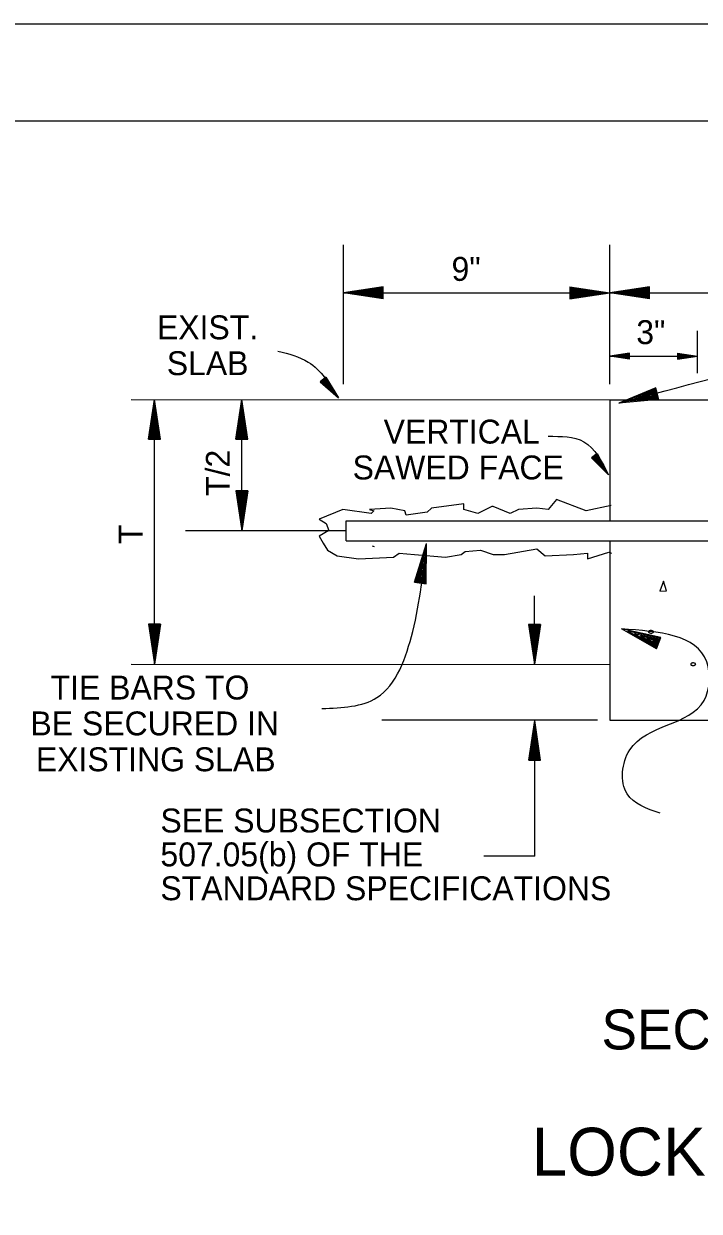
# Model space of a CAD drawing. Extents: x 1375738 to 1375905, y 380661 to 380875.
# Drawn here: x 1375777.18 to 1375790.75, y 380850.89 to 380874.73 of the extents above; entities that cross this region are included whole.
import ezdxf

# ---------------------------------------------------------------- set-up
doc = ezdxf.new("R2010")
doc.units = 0
for name, color, linetype in [('R_Border', 7, 'Continuous'), ('R_Draft', 7, 'Continuous'), ('R_No Plot', 7, 'Continuous')]:
    doc.layers.add(name, color=color, linetype=linetype)

msp = doc.modelspace()

# ---------------------------------------------------------------- linework, layer by layer
at = {"layer": 'R_Border'}
msp.add_line((1375744.419, 380872.783), (1375902.509, 380872.783), dxfattribs=at)
at = {"layer": 'R_Draft'}
for p, q in [((1375783.599, 380867.494), (1375783.599, 380870.291)), ((1375788.949, 380867.494), (1375788.949, 380870.291)), ((1375784.399, 380869.449), (1375783.599, 380869.329)), ((1375783.599, 380869.329), (1375788.949, 380869.329)), ((1375784.399, 380869.209), (1375783.599, 380869.329)), ((1375784.399, 380869.429), (1375783.733, 380869.329)), ((1375784.399, 380869.229), (1375783.733, 380869.329)), ((1375784.399, 380869.409), (1375783.87, 380869.329)), ((1375784.399, 380869.25), (1375783.87, 380869.329)), ((1375784.399, 380869.389), (1375784.004, 380869.329)), ((1375784.399, 380869.27), (1375784.004, 380869.329)), ((1375784.399, 380869.369), (1375784.139, 380869.329)), ((1375784.399, 380869.291), (1375784.139, 380869.329)), ((1375784.399, 380869.348), (1375784.273, 380869.329)), ((1375784.399, 380869.311), (1375784.273, 380869.329)), ((1375784.399, 380869.209), (1375784.399, 380869.449)), ((1375788.149, 380869.449), (1375788.949, 380869.329)), ((1375788.149, 380869.449), (1375788.149, 380869.209)), ((1375788.149, 380869.429), (1375788.815, 380869.329)), ((1375788.149, 380869.409), (1375788.678, 380869.329)), ((1375788.149, 380869.389), (1375788.544, 380869.329)), ((1375788.149, 380869.368), (1375788.409, 380869.329)), ((1375788.149, 380869.348), (1375788.275, 380869.329)), ((1375788.149, 380869.209), (1375788.949, 380869.329)), ((1375788.149, 380869.29), (1375788.409, 380869.329)), ((1375788.149, 380869.25), (1375788.678, 380869.329)), ((1375788.149, 380869.229), (1375788.815, 380869.329)), ((1375788.149, 380869.27), (1375788.544, 380869.329)), ((1375788.149, 380869.311), (1375788.275, 380869.329)), ((1375789.749, 380869.449), (1375788.949, 380869.329)), ((1375788.949, 380869.329), (1375794.403, 380869.329)), ((1375789.749, 380869.209), (1375788.949, 380869.329)), ((1375789.749, 380869.429), (1375789.082, 380869.329)), ((1375789.749, 380869.229), (1375789.082, 380869.329)), ((1375789.749, 380869.409), (1375789.22, 380869.329)), ((1375789.749, 380869.25), (1375789.22, 380869.329)), ((1375789.749, 380869.389), (1375789.353, 380869.329)), ((1375789.749, 380869.27), (1375789.353, 380869.329)), ((1375789.749, 380869.369), (1375789.489, 380869.329)), ((1375789.749, 380869.291), (1375789.489, 380869.329)), ((1375789.749, 380869.348), (1375789.622, 380869.329)), ((1375789.749, 380869.311), (1375789.622, 380869.329)), ((1375789.749, 380869.209), (1375789.749, 380869.449)), ((1375790.71, 380867.719), (1375790.71, 380868.567)), ((1375789.349, 380868.119), (1375788.949, 380868.059)), ((1375788.949, 380868.059), (1375790.71, 380868.059)), ((1375789.349, 380867.999), (1375788.949, 380868.059)), ((1375789.349, 380868.109), (1375789.016, 380868.059)), ((1375789.349, 380868.009), (1375789.016, 380868.059)), ((1375789.349, 380868.098), (1375789.084, 380868.059)), ((1375789.349, 380868.019), (1375789.084, 380868.059)), ((1375789.349, 380868.088), (1375789.151, 380868.059)), ((1375789.349, 380868.029), (1375789.151, 380868.059)), ((1375789.349, 380868.078), (1375789.219, 380868.059)), ((1375789.349, 380868.039), (1375789.219, 380868.059)), ((1375789.349, 380868.068), (1375789.286, 380868.059)), ((1375789.349, 380868.049), (1375789.286, 380868.059)), ((1375789.349, 380867.999), (1375789.349, 380868.119)), ((1375790.31, 380868.119), (1375790.71, 380868.059)), ((1375790.31, 380868.119), (1375790.31, 380867.999)), ((1375790.31, 380868.109), (1375790.643, 380868.059)), ((1375790.31, 380868.098), (1375790.574, 380868.059)), ((1375790.31, 380868.088), (1375790.508, 380868.059)), ((1375790.31, 380868.078), (1375790.44, 380868.059)), ((1375790.31, 380868.068), (1375790.373, 380868.059)), ((1375790.31, 380867.999), (1375790.71, 380868.059)), ((1375790.31, 380868.039), (1375790.44, 380868.059)), ((1375790.31, 380868.019), (1375790.574, 380868.059)), ((1375790.31, 380868.009), (1375790.643, 380868.059)), ((1375790.31, 380868.029), (1375790.508, 380868.059)), ((1375790.31, 380868.049), (1375790.373, 380868.059)), ((1375783.244, 380867.635), (1375783.134, 380867.542)), ((1375783.171, 380867.573), (1375783.29, 380867.469)), ((1375783.18, 380867.581), (1375783.238, 380867.53)), ((1375783.198, 380867.595), (1375783.238, 380867.53)), ((1375783.207, 380867.603), (1375783.29, 380867.469)), ((1375783.216, 380867.611), (1375783.342, 380867.407)), ((1375783.226, 380867.619), (1375783.394, 380867.346)), ((1375783.235, 380867.627), (1375783.448, 380867.283)), ((1375783.244, 380867.635), (1375783.499, 380867.222)), ((1375783.134, 380867.542), (1375783.499, 380867.222)), ((1375783.143, 380867.549), (1375783.448, 380867.283)), ((1375783.153, 380867.557), (1375783.394, 380867.346)), ((1375783.162, 380867.565), (1375783.342, 380867.407)), ((1375789.878, 380867.422), (1375789.131, 380867.111)), ((1375789.883, 380867.402), (1375789.261, 380867.144)), ((1375789.888, 380867.383), (1375789.394, 380867.177)), ((1375789.893, 380867.363), (1375789.524, 380867.209)), ((1375789.898, 380867.343), (1375789.655, 380867.242)), ((1375789.936, 380867.189), (1375789.878, 380867.422)), ((1375779.334, 380867.189), (1375788.952, 380867.184)), ((1375779.684, 380866.388), (1375779.804, 380867.188)), ((1375779.804, 380861.875), (1375779.804, 380867.188)), ((1375779.924, 380866.388), (1375779.804, 380867.188)), ((1375781.436, 380866.388), (1375781.556, 380867.188)), ((1375781.556, 380864.554), (1375781.556, 380867.188)), ((1375781.676, 380866.388), (1375781.556, 380867.188)), ((1375788.949, 380867.184), (1375798.81, 380867.184)), ((1375788.949, 380867.184), (1375788.949, 380864.752)), ((1375789.936, 380867.189), (1375789.131, 380867.111)), ((1375789.932, 380867.208), (1375789.261, 380867.144)), ((1375789.927, 380867.228), (1375789.394, 380867.177)), ((1375789.922, 380867.247), (1375789.524, 380867.209)), ((1375789.917, 380867.268), (1375789.655, 380867.242)), ((1375789.903, 380867.324), (1375789.785, 380867.275)), ((1375789.912, 380867.287), (1375789.785, 380867.275)), ((1375779.704, 380866.388), (1375779.804, 380867.055)), ((1375779.724, 380866.388), (1375779.804, 380866.917)), ((1375779.904, 380866.388), (1375779.804, 380867.055)), ((1375779.883, 380866.388), (1375779.804, 380866.917)), ((1375781.456, 380866.388), (1375781.556, 380867.055)), ((1375781.476, 380866.388), (1375781.556, 380866.917)), ((1375781.656, 380866.388), (1375781.556, 380867.055)), ((1375781.635, 380866.388), (1375781.556, 380866.917)), ((1375779.744, 380866.388), (1375779.804, 380866.784)), ((1375779.765, 380866.388), (1375779.804, 380866.648)), ((1375779.863, 380866.388), (1375779.804, 380866.784)), ((1375779.843, 380866.388), (1375779.804, 380866.648)), ((1375781.496, 380866.388), (1375781.556, 380866.784)), ((1375781.517, 380866.388), (1375781.556, 380866.648)), ((1375781.615, 380866.388), (1375781.556, 380866.784)), ((1375781.595, 380866.388), (1375781.556, 380866.648)), ((1375779.684, 380866.388), (1375779.924, 380866.388)), ((1375779.785, 380866.388), (1375779.804, 380866.515)), ((1375779.822, 380866.388), (1375779.804, 380866.515)), ((1375781.436, 380866.388), (1375781.676, 380866.388)), ((1375781.537, 380866.388), (1375781.556, 380866.515)), ((1375781.574, 380866.388), (1375781.556, 380866.515)), ((1375788.695, 380866.103), (1375788.58, 380866.017)), ((1375788.58, 380866.017), (1375788.925, 380865.676)), ((1375788.589, 380866.024), (1375788.877, 380865.74)), ((1375788.599, 380866.031), (1375788.828, 380865.806)), ((1375788.608, 380866.038), (1375788.78, 380865.87)), ((1375788.618, 380866.046), (1375788.731, 380865.935)), ((1375788.628, 380866.053), (1375788.683, 380865.999)), ((1375788.646, 380866.067), (1375788.683, 380865.999)), ((1375788.656, 380866.074), (1375788.731, 380865.935)), ((1375788.666, 380866.081), (1375788.78, 380865.87)), ((1375788.676, 380866.089), (1375788.828, 380865.806)), ((1375788.685, 380866.096), (1375788.877, 380865.74)), ((1375788.695, 380866.103), (1375788.925, 380865.676)), ((1375781.436, 380865.354), (1375781.556, 380864.554)), ((1375781.676, 380865.354), (1375781.436, 380865.354)), ((1375781.456, 380865.354), (1375781.556, 380864.687)), ((1375781.476, 380865.354), (1375781.556, 380864.825)), ((1375781.496, 380865.354), (1375781.556, 380864.958)), ((1375781.516, 380865.354), (1375781.556, 380865.094)), ((1375781.537, 380865.354), (1375781.556, 380865.227)), ((1375781.676, 380865.354), (1375781.556, 380864.554)), ((1375781.594, 380865.354), (1375781.556, 380865.094)), ((1375781.635, 380865.354), (1375781.556, 380864.825)), ((1375781.656, 380865.354), (1375781.556, 380864.687)), ((1375781.615, 380865.354), (1375781.556, 380864.958)), ((1375781.574, 380865.354), (1375781.556, 380865.227)), ((1375783.657, 380864.755), (1375794.47, 380864.749)), ((1375783.657, 380864.353), (1375783.657, 380864.755)), ((1375783.657, 380864.554), (1375780.426, 380864.554)), ((1375783.657, 380864.353), (1375794.469, 380864.347)), ((1375785.024, 380863.523), (1375785.266, 380864.295)), ((1375785.261, 380863.487), (1375785.266, 380864.295)), ((1375788.949, 380864.351), (1375788.949, 380860.751)), ((1375785.044, 380863.521), (1375785.245, 380864.163)), ((1375785.064, 380863.517), (1375785.224, 380864.027)), ((1375785.221, 380863.493), (1375785.224, 380864.027)), ((1375785.241, 380863.489), (1375785.245, 380864.163)), ((1375785.084, 380863.514), (1375785.204, 380863.896)), ((1375785.104, 380863.511), (1375785.183, 380863.762)), ((1375785.181, 380863.499), (1375785.183, 380863.762)), ((1375785.202, 380863.496), (1375785.204, 380863.896)), ((1375785.024, 380863.523), (1375785.261, 380863.487)), ((1375785.124, 380863.508), (1375785.162, 380863.63)), ((1375785.161, 380863.502), (1375785.162, 380863.63)), ((1375787.44, 380861.874), (1375787.44, 380863.248)), ((1375779.684, 380862.675), (1375779.804, 380861.875)), ((1375779.924, 380862.675), (1375779.684, 380862.675)), ((1375779.704, 380862.675), (1375779.804, 380862.009)), ((1375779.724, 380862.675), (1375779.804, 380862.147)), ((1375779.744, 380862.675), (1375779.804, 380862.28)), ((1375779.764, 380862.675), (1375779.804, 380862.415)), ((1375779.785, 380862.675), (1375779.804, 380862.549)), ((1375779.924, 380862.675), (1375779.804, 380861.875)), ((1375779.842, 380862.675), (1375779.804, 380862.415)), ((1375779.883, 380862.675), (1375779.804, 380862.147)), ((1375779.904, 380862.675), (1375779.804, 380862.009)), ((1375779.863, 380862.675), (1375779.804, 380862.28)), ((1375779.822, 380862.675), (1375779.804, 380862.549)), ((1375787.32, 380862.674), (1375787.44, 380861.874)), ((1375787.56, 380862.674), (1375787.32, 380862.674)), ((1375787.34, 380862.674), (1375787.44, 380862.008)), ((1375787.36, 380862.674), (1375787.44, 380862.145)), ((1375787.38, 380862.674), (1375787.44, 380862.279)), ((1375787.401, 380862.674), (1375787.44, 380862.414)), ((1375787.421, 380862.674), (1375787.44, 380862.548)), ((1375787.56, 380862.674), (1375787.44, 380861.874)), ((1375787.479, 380862.674), (1375787.44, 380862.414)), ((1375787.52, 380862.674), (1375787.44, 380862.145)), ((1375787.54, 380862.674), (1375787.44, 380862.008)), ((1375787.5, 380862.674), (1375787.44, 380862.279)), ((1375787.459, 380862.674), (1375787.44, 380862.548)), ((1375789.889, 380862.183), (1375789.186, 380862.583)), ((1375789.976, 380862.407), (1375789.186, 380862.583)), ((1375789.896, 380862.201), (1375789.311, 380862.535)), ((1375789.968, 380862.388), (1375789.311, 380862.535)), ((1375789.961, 380862.369), (1375789.439, 380862.485)), ((1375789.904, 380862.221), (1375789.439, 380862.485)), ((1375789.911, 380862.239), (1375789.564, 380862.437)), ((1375789.954, 380862.35), (1375789.564, 380862.437)), ((1375789.947, 380862.331), (1375789.69, 380862.389)), ((1375789.918, 380862.259), (1375789.69, 380862.389)), ((1375789.939, 380862.312), (1375789.814, 380862.34)), ((1375789.926, 380862.277), (1375789.814, 380862.34)), ((1375789.889, 380862.183), (1375789.976, 380862.407)), ((1375779.331, 380861.876), (1375788.949, 380861.871)), ((1375788.7, 380860.751), (1375784.372, 380860.751)), ((1375787.321, 380859.945), (1375787.441, 380860.745)), ((1375787.442, 380858.018), (1375787.441, 380860.745)), ((1375787.561, 380859.945), (1375787.441, 380860.745)), ((1375788.949, 380860.751), (1375798.81, 380860.751)), ((1375787.341, 380859.945), (1375787.441, 380860.611)), ((1375787.362, 380859.945), (1375787.441, 380860.473)), ((1375787.541, 380859.945), (1375787.441, 380860.611)), ((1375787.521, 380859.945), (1375787.441, 380860.473)), ((1375787.382, 380859.945), (1375787.441, 380860.34)), ((1375787.402, 380859.945), (1375787.441, 380860.205)), ((1375787.501, 380859.945), (1375787.441, 380860.34)), ((1375787.48, 380859.945), (1375787.441, 380860.205)), ((1375787.321, 380859.945), (1375787.561, 380859.945)), ((1375787.422, 380859.945), (1375787.441, 380860.071)), ((1375787.46, 380859.945), (1375787.441, 380860.071)), ((1375787.442, 380858.018), (1375786.417, 380858.018))]:
    msp.add_line(p, q, dxfattribs=at)
for points in [[(1375788.975, 380865.06), (1375788.474, 380864.952), (1375787.881, 380865.178), (1375787.712, 380864.981), (1375787.486, 380865.009), (1375787.118, 380864.981), (1375786.949, 380864.896), (1375786.61, 380865.037), (1375786.582, 380865.037), (1375786.3, 380864.896), (1375786.017, 380864.981), (1375786.017, 380865.093), (1375785.368, 380865.009), (1375785.283, 380864.924), (1375784.86, 380864.867), (1375784.831, 380864.952), (1375784.549, 380865.009), (1375784.125, 380864.981), (1375784.21, 380864.952), (1375784.154, 380864.896), (1375783.589, 380864.981), (1375783.109, 380864.783), (1375783.25, 380864.698), (1375783.306, 380864.557), (1375783.109, 380864.444), (1375783.193, 380864.303), (1375783.278, 380864.161), (1375783.476, 380864.049), (1375783.899, 380863.992), (1375784.605, 380864.02), (1375784.718, 380864.105), (1375785.029, 380864.077), (1375785.65, 380864.02), (1375785.961, 380864.077), (1375786.046, 380864.133), (1375786.356, 380864.161), (1375786.61, 380864.077), (1375786.836, 380864.077), (1375787.486, 380864.19), (1375787.655, 380864.049), (1375788.22, 380864.077), (1375788.502, 380864.105), (1375788.502, 380863.992), (1375788.931, 380864.123), (1375788.982, 380864.105)], [(1375784.177, 380864.252), (1375784.215, 380864.238)], [(1375790.028, 380863.54), (1375789.956, 380863.341), (1375790.088, 380863.346), (1375790.028, 380863.54)]]:
    msp.add_lwpolyline(points, dxfattribs=at)
for points in [[(1375789.131, 380867.111), (1375792.886, 380868.05), (1375795.249, 380868.487)], [(1375782.284, 380868.16), (1375782.892, 380867.939), (1375783.499, 380867.222)], [(1375787.71, 380866.449), (1375788.428, 380866.338), (1375788.925, 380865.676)], [(1375783.168, 380860.982), (1375784.272, 380861.203), (1375784.99, 380862.528), (1375785.266, 380864.295)], [(1375789.96, 380858.884), (1375789.297, 380859.271), (1375789.352, 380860.154), (1375790.843, 380861.148), (1375790.898, 380861.921), (1375789.186, 380862.583)], [(1375789.778, 380862.548), (1375789.796, 380862.546), (1375789.816, 380862.539), (1375789.827, 380862.529), (1375789.828, 380862.523), (1375789.823, 380862.512), (1375789.817, 380862.507), (1375789.804, 380862.502), (1375789.787, 380862.498), (1375789.778, 380862.498), (1375789.765, 380862.499), (1375789.751, 380862.502), (1375789.74, 380862.507), (1375789.73, 380862.516), (1375789.728, 380862.523), (1375789.732, 380862.533), (1375789.74, 380862.539), (1375789.748, 380862.543), (1375789.76, 380862.546), (1375789.767, 380862.548), (1375789.778, 380862.548)], [(1375790.626, 380861.899), (1375790.643, 380861.897), (1375790.664, 380861.889), (1375790.674, 380861.879), (1375790.676, 380861.873), (1375790.67, 380861.863), (1375790.664, 380861.858), (1375790.652, 380861.852), (1375790.634, 380861.849), (1375790.626, 380861.849), (1375790.612, 380861.85), (1375790.598, 380861.852), (1375790.587, 380861.857), (1375790.577, 380861.867), (1375790.576, 380861.873), (1375790.579, 380861.883), (1375790.587, 380861.889), (1375790.595, 380861.893), (1375790.607, 380861.897), (1375790.614, 380861.898), (1375790.626, 380861.899)]]:
    msp.add_spline(points, degree=3, dxfattribs=at)
at = {"layer": 'R_No Plot'}
msp.add_line((1375738.219, 380874.73), (1375904.885, 380874.73), dxfattribs=at)
for points in [[(1375738.215, 380874.73), (1375904.885, 380874.73), (1375904.885, 380768.061), (1375738.215, 380768.061)], [(1375861.379, 380872.783), (1375871.189, 380872.783), (1375871.189, 380867.843), (1375879.245, 380867.843), (1375890.845, 380867.843), (1375890.845, 380851.508), (1375902.449, 380851.508), (1375902.509, 380770.053), (1375744.419, 380770.053), (1375744.419, 380872.783)]]:
    msp.add_lwpolyline(points, close=True, dxfattribs=at)

# ---------------------------------------------------------------- texts
at = {"layer": 'R_Draft'}
for s, height, p in [('9"', 0.48, (1375785.771, 380869.569)), ('EXIST.', 0.48, (1375779.852, 380868.396)), ('3"', 0.48, (1375789.482, 380868.299)), ('SLAB', 0.48, (1375780.05, 380867.676)), ('VERTICAL', 0.48, (1375784.407, 380866.303)), ('SAWED FACE', 0.48, (1375783.783, 380865.583)), ('TIE BARS TO', 0.48, (1375777.715, 380861.165)), ('BE SECURED IN', 0.48, (1375777.311, 380860.445)), ('EXISTING SLAB', 0.48, (1375777.42, 380859.725)), ('SEE SUBSECTION', 0.48, (1375779.922, 380858.496)), ('507.05(b) OF THE', 0.48, (1375779.922, 380857.816)), ('STANDARD SPECIFICATIONS', 0.48, (1375779.922, 380857.136)), ('SECTION D-D', 0.8, (1375788.783, 380854.141)), ('LOCKED JOINT', 0.96, (1375787.38, 380851.609))]:
    msp.add_text(s, height=height, dxfattribs=at).set_placement(p)
for s, p in [('T/2', (1375781.316, 380865.251)), ('T', (1375779.564, 380864.287))]:
    msp.add_text(s, height=0.48, rotation=90, dxfattribs=at).set_placement(p)

doc.saveas('drawing.dxf')
